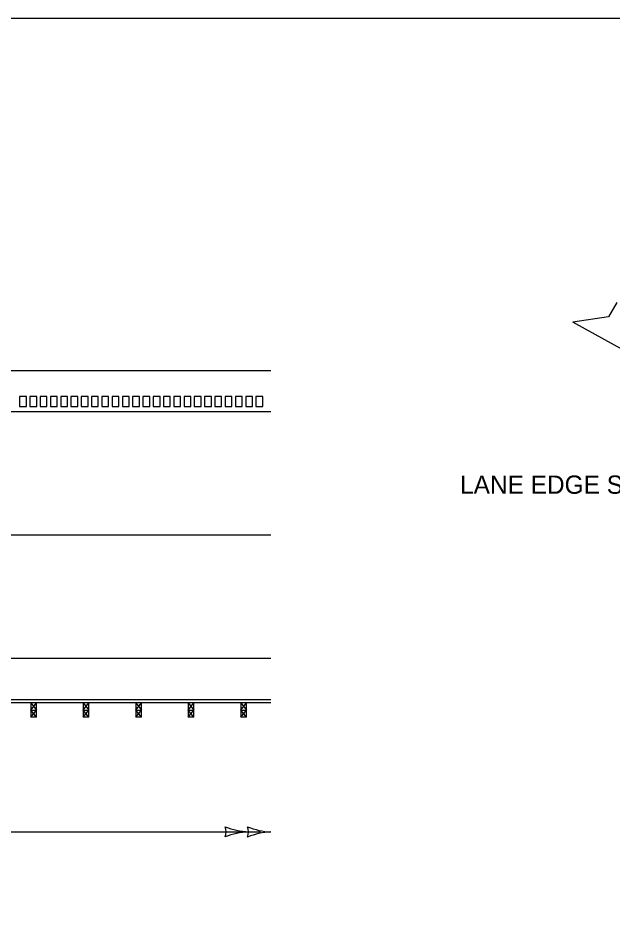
# Model space of a CAD drawing. Extents: x 49991.4 to 50021, y 49987.6 to 50011.4.
# Drawn here: x 50010.499 to 50012.452, y 49996.035 to 49998.999 of the extents above; entities that cross this region are included whole.
import ezdxf

# ---------------------------------------------------------------- set-up
doc = ezdxf.new("R2010")
doc.units = 0
for name, color, linetype in [('Level 1', 7, 'Continuous'), ('Level 2', 7, 'Continuous'), ('Level 3', 7, 'Continuous')]:
    doc.layers.add(name, color=color, linetype=linetype)

msp = doc.modelspace()

# ---------------------------------------------------------------- linework, layer by layer
at = {"layer": 'Level 1'}
for p, q in [((50012.4655, 49998.065), (50012.4382, 49998.018)), ((50012.4382, 49998.018), (50012.3203, 49998.0008)), ((50015.3448, 49996.3328), (50012.3203, 49998.0008)), ((50011.3288, 49997.8413), (50005.1053, 49997.8413)), ((50011.3288, 49997.7063), (50005.1053, 49997.7063)), ((50011.3288, 49997.3013), (50005.1053, 49997.3013)), ((50011.3288, 49996.8963), (50005.1053, 49996.8963)), ((50011.3288, 49996.7613), (50009.3237, 49996.7613)), ((50011.3288, 49996.7613), (50009.4632, 49996.7613)), ((50011.3288, 49996.7509), (50009.3237, 49996.7509)), ((50010.5403, 49996.7509), (50010.5589, 49996.7276)), ((50010.5403, 49996.7276), (50010.5589, 49996.7509)), ((50010.5403, 49996.7509), (50010.5403, 49996.7043)), ((50010.5589, 49996.7043), (50010.5403, 49996.7276)), ((50010.5403, 49996.7043), (50010.5589, 49996.7276)), ((50010.5403, 49996.7276), (50010.5589, 49996.7276)), ((50010.5589, 49996.7043), (50010.5589, 49996.7509)), ((50010.7128, 49996.7509), (50010.7314, 49996.7276)), ((50010.7128, 49996.7276), (50010.7314, 49996.7509)), ((50010.7128, 49996.7509), (50010.7128, 49996.7043)), ((50010.7314, 49996.7043), (50010.7128, 49996.7276)), ((50010.7128, 49996.7043), (50010.7314, 49996.7276)), ((50010.7128, 49996.7276), (50010.7314, 49996.7276)), ((50010.7314, 49996.7043), (50010.7314, 49996.7509)), ((50010.8853, 49996.7509), (50010.9039, 49996.7276)), ((50010.8853, 49996.7276), (50010.9039, 49996.7509)), ((50010.8853, 49996.7509), (50010.8853, 49996.7043)), ((50010.9039, 49996.7043), (50010.8853, 49996.7276)), ((50010.8853, 49996.7043), (50010.9039, 49996.7276)), ((50010.8853, 49996.7276), (50010.9039, 49996.7276)), ((50010.9039, 49996.7043), (50010.9039, 49996.7509)), ((50011.0578, 49996.7509), (50011.0764, 49996.7276)), ((50011.0578, 49996.7276), (50011.0764, 49996.7509)), ((50011.0578, 49996.7509), (50011.0578, 49996.7043)), ((50011.0764, 49996.7043), (50011.0578, 49996.7276)), ((50011.0578, 49996.7043), (50011.0764, 49996.7276)), ((50011.0578, 49996.7276), (50011.0764, 49996.7276)), ((50011.0764, 49996.7043), (50011.0764, 49996.7509)), ((50011.2303, 49996.7509), (50011.2489, 49996.7276)), ((50011.2303, 49996.7276), (50011.2489, 49996.7509)), ((50011.2303, 49996.7509), (50011.2303, 49996.7043)), ((50011.2489, 49996.7043), (50011.2303, 49996.7276)), ((50011.2303, 49996.7043), (50011.2489, 49996.7276)), ((50011.2303, 49996.7276), (50011.2489, 49996.7276)), ((50011.2489, 49996.7043), (50011.2489, 49996.7509)), ((50010.5589, 49996.7043), (50010.5403, 49996.7043)), ((50010.7314, 49996.7043), (50010.7128, 49996.7043)), ((50010.9039, 49996.7043), (50010.8853, 49996.7043)), ((50011.0764, 49996.7043), (50011.0578, 49996.7043)), ((50011.2489, 49996.7043), (50011.2303, 49996.7043))]:
    msp.add_line(p, q, dxfattribs=at)
for points in [[(49999.3835, 49998.9992), (50016.7501, 49998.9992), (50016.7501, 49987.7988), (49999.3835, 49987.7988)], [(50010.5037, 49997.7235), (50010.5261, 49997.7235), (50010.5261, 49997.7572), (50010.5037, 49997.7572)], [(50010.5375, 49997.7235), (50010.5599, 49997.7235), (50010.5599, 49997.7572), (50010.5375, 49997.7572)], [(50010.5712, 49997.7235), (50010.5936, 49997.7235), (50010.5936, 49997.7572), (50010.5712, 49997.7572)], [(50010.6049, 49997.7235), (50010.6273, 49997.7235), (50010.6273, 49997.7572), (50010.6049, 49997.7572)], [(50010.6387, 49997.7235), (50010.6611, 49997.7235), (50010.6611, 49997.7572), (50010.6387, 49997.7572)], [(50010.6725, 49997.7235), (50010.6949, 49997.7235), (50010.6949, 49997.7572), (50010.6725, 49997.7572)], [(50010.7062, 49997.7235), (50010.7286, 49997.7235), (50010.7286, 49997.7572), (50010.7062, 49997.7572)], [(50010.7399, 49997.7235), (50010.7623, 49997.7235), (50010.7623, 49997.7572), (50010.7399, 49997.7572)], [(50010.7737, 49997.7235), (50010.7961, 49997.7235), (50010.7961, 49997.7572), (50010.7737, 49997.7572)], [(50010.8075, 49997.7235), (50010.8299, 49997.7235), (50010.8299, 49997.7572), (50010.8075, 49997.7572)], [(50010.8412, 49997.7235), (50010.8636, 49997.7235), (50010.8636, 49997.7572), (50010.8412, 49997.7572)], [(50010.8749, 49997.7235), (50010.8973, 49997.7235), (50010.8973, 49997.7572), (50010.8749, 49997.7572)], [(50010.9087, 49997.7235), (50010.9311, 49997.7235), (50010.9311, 49997.7572), (50010.9087, 49997.7572)], [(50010.9425, 49997.7235), (50010.9649, 49997.7235), (50010.9649, 49997.7572), (50010.9425, 49997.7572)], [(50010.9762, 49997.7235), (50010.9986, 49997.7235), (50010.9986, 49997.7572), (50010.9762, 49997.7572)], [(50011.0099, 49997.7235), (50011.0323, 49997.7235), (50011.0323, 49997.7572), (50011.0099, 49997.7572)], [(50011.0437, 49997.7235), (50011.0661, 49997.7235), (50011.0661, 49997.7572), (50011.0437, 49997.7572)], [(50011.0775, 49997.7235), (50011.0999, 49997.7235), (50011.0999, 49997.7572), (50011.0775, 49997.7572)], [(50011.1112, 49997.7235), (50011.1336, 49997.7235), (50011.1336, 49997.7572), (50011.1112, 49997.7572)], [(50011.1449, 49997.7235), (50011.1673, 49997.7235), (50011.1673, 49997.7572), (50011.1449, 49997.7572)], [(50011.1787, 49997.7235), (50011.2011, 49997.7235), (50011.2011, 49997.7572), (50011.1787, 49997.7572)], [(50011.2125, 49997.7235), (50011.2349, 49997.7235), (50011.2349, 49997.7572), (50011.2125, 49997.7572)], [(50011.2463, 49997.7235), (50011.2687, 49997.7235), (50011.2687, 49997.7572), (50011.2463, 49997.7572)], [(50011.28, 49997.7235), (50011.3024, 49997.7235), (50011.3024, 49997.7572), (50011.28, 49997.7572)]]:
    msp.add_lwpolyline(points, close=True, dxfattribs=at)
at = {"layer": 'Level 3'}
msp.add_line((50007.3851, 49996.3278), (50011.2951, 49996.3278), dxfattribs=at)
for centre, radius, start, end in [((50011.2643, 49996.5499), 0.2223, 247.456, 267.6395), ((50011.127, 49996.3278), 0.0548, 342.1388, 17.8612), ((50011.3378, 49996.5497), 0.2223, 247.456, 267.6395), ((50011.2004, 49996.3275), 0.0548, 342.1388, 17.8612), ((50011.2667, 49996.0951), 0.233, 92.8273, 112.0772), ((50011.3401, 49996.0948), 0.233, 92.8273, 112.0772)]:
    msp.add_arc(centre, radius, start, end, dxfattribs=at)

# ---------------------------------------------------------------- texts
at = {"layer": 'Level 2'}
msp.add_text('LANE EDGE STRIPE', height=0.06, dxfattribs=at).set_placement((50011.9503, 49997.4375))

doc.saveas('drawing.dxf')
